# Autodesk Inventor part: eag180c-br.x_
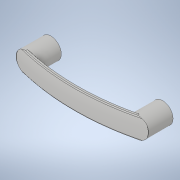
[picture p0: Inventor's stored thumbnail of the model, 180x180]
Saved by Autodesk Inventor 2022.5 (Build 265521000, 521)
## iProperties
Created: 2021-07
Part Number: eag180c-br.x_
Material: 一般
Document SubType Name: Modeling
Designer: ImaoCorp
Density: 1 g/cm^3
Appearance: 既定
Sending System: SOLIDWORKS 2019-2019304
MC: AMD64
MC_MODEL: Intel64 Family 6 Model 60 Stepping 3, GenuineIntel
OS: Windows_NT
FRU: Parasolid Version 31.0, build 290,  9- 1-2019
FORMAT: text
GUISE: transmit
KEY: eag180c-br
FILE: eag180c-br.x_t
DATE: Thu Jul 29 14:21:57 2021
Author: ImaoCorp
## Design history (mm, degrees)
feature "Base1"
node "ソリッド1"
